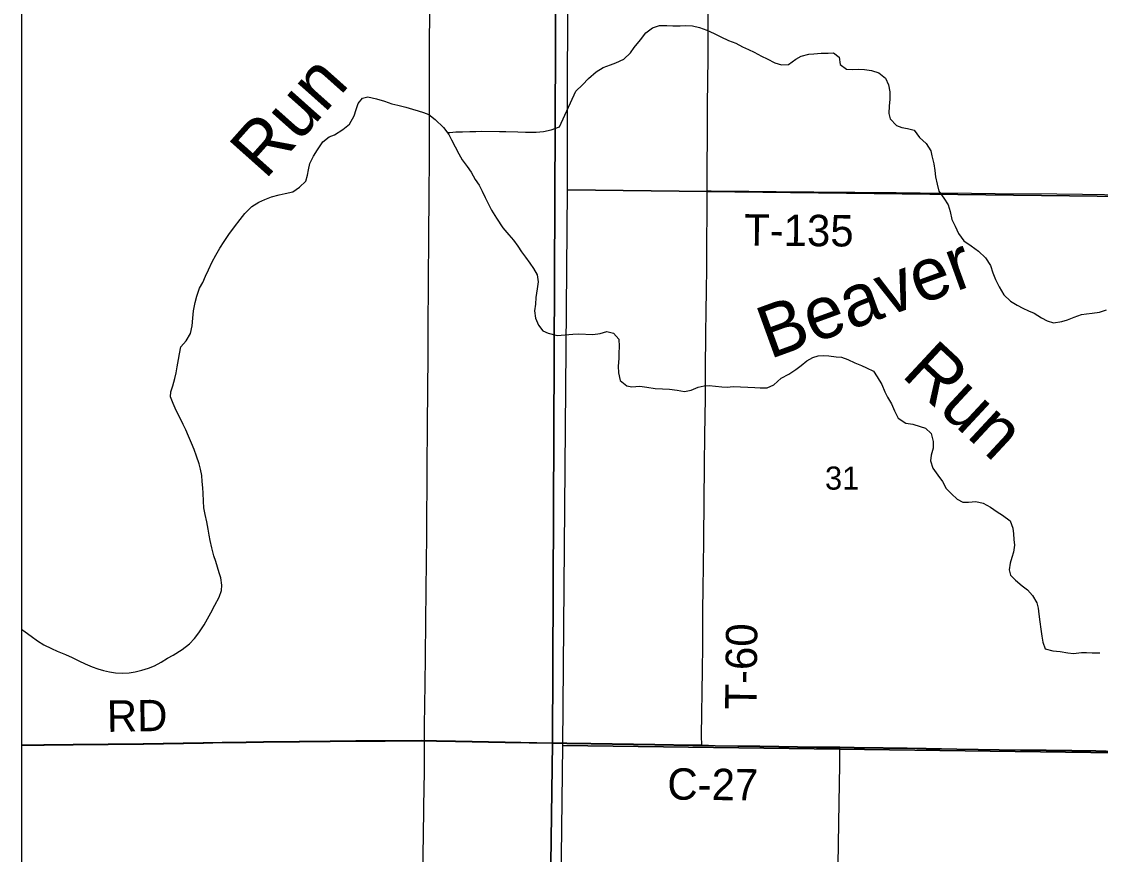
# Model space of a CAD drawing. Extents: x 0 to 34, y 0 to 22.
# Drawn here: x 2 to 3.955, y 15.508 to 17.017 of the extents above; entities that cross this region are included whole.
import ezdxf

# ---------------------------------------------------------------- set-up
doc = ezdxf.new("R2010")
doc.units = 0
for name, color, linetype in [('Default', 7, 'Continuous'), ('GM_X_City_Street', 7, 'Continuous'), ('GM_X_County_Road', 7, 'Continuous'), ('GM_X_County_Road_Text', 7, 'Continuous'), ('GM_X_Interchange_Ramps', 7, 'Continuous'), ('GM_X_Major_River_Text', 7, 'Continuous'), ('GM_X_Minor_River', 7, 'Continuous'), ('GM_X_Minor_River_Text', 7, 'Continuous'), ('GM_X_Section', 7, 'Continuous'), ('GM_X_Unincorporated_Location', 7, 'Continuous'), ('SH_Cut_Line', 7, 'Continuous'), ('SH_Text', 7, 'Continuous')]:
    doc.layers.add(name, color=color, linetype=linetype)

msp = doc.modelspace()

# ---------------------------------------------------------------- linework, layer by layer
at = {"layer": 'Default'}
for points in [[(2, 20.8), (2, 15.7064), (2.0405, 15.7068), (2.0933, 15.7073), (2.2206, 15.7088), (2.3293, 15.7107), (2.3635, 15.7113), (2.407, 15.7118), (2.4381, 15.7123), (2.5033, 15.7129), (2.5592, 15.7135), (2.6058, 15.714), (2.6587, 15.7141), (2.7239, 15.7144), (2.73, 15.7143), (2.7519, 15.714), (2.786, 15.7133), (2.8761, 15.7117), (2.9623, 15.7101), (2.9708, 17.6769)], [(2.9708, 17.6769), (2.9623, 15.7101), (2.988, 15.7097), (3.0317, 15.7091), (3.1473, 15.7074), (3.216, 15.7061), (3.2324, 15.706), (3.257, 15.7053), (3.3377, 15.7042), (3.4402, 15.7026), (3.4828, 15.7023), (3.5086, 15.702), (3.5614, 15.7014), (3.6049, 15.701), (3.639, 15.7003), (3.6949, 15.6992), (3.8099, 15.6974), (3.8565, 15.6969), (3.9031, 15.6964), (3.9466, 15.6957), (3.9843, 15.695)], [(3.9843, 15.695), (3.9466, 15.6957), (3.9031, 15.6964), (3.8565, 15.6969), (3.8099, 15.6974), (3.6949, 15.6992), (3.639, 15.7003), (3.6049, 15.701), (3.5614, 15.7014), (3.5086, 15.702), (3.4828, 15.7023), (3.4402, 15.7026), (3.3377, 15.7042), (3.257, 15.7053), (3.2324, 15.706), (3.216, 15.7061), (3.1473, 15.7074), (3.0317, 15.7091), (2.988, 15.7097), (2.9623, 15.7101), (2.9479, 14.7065), (2.9377, 14), (7.9275, 14)]]:
    msp.add_lwpolyline(points, dxfattribs=at)
msp.add_lwpolyline([(2, 15.7064), (2, 14), (2.9377, 14), (2.9479, 14.7065), (2.9623, 15.7101), (2.8761, 15.7117), (2.786, 15.7133), (2.7519, 15.714), (2.73, 15.7143), (2.7239, 15.7144), (2.6587, 15.7141), (2.6058, 15.714), (2.5592, 15.7135), (2.5033, 15.7129), (2.4381, 15.7123), (2.407, 15.7118), (2.3635, 15.7113), (2.3293, 15.7107), (2.2206, 15.7088), (2.0933, 15.7073), (2.0405, 15.7068)], close=True, dxfattribs=at)
at = {"layer": 'GM_X_City_Street'}
for points in [[(2, 15.7059), (2.0407, 15.7063), (2.0935, 15.7068), (2.2208, 15.7083), (2.3296, 15.7101), (2.3637, 15.7108), (2.4072, 15.7113), (2.4383, 15.7117), (2.5035, 15.7124), (2.5594, 15.7129), (2.6061, 15.7135), (2.6589, 15.7135), (2.7241, 15.7139), (2.7302, 15.7138)], [(2.7302, 15.7138), (2.7521, 15.7135), (2.7863, 15.7128), (2.8763, 15.7112), (2.9625, 15.7096)], [(2.9625, 15.7096), (2.9882, 15.7092), (3.0319, 15.7086), (3.1475, 15.7069), (3.2162, 15.7056), (3.2326, 15.7055)], [(3.2326, 15.7055), (3.2572, 15.7048), (3.338, 15.7037), (3.4405, 15.7021), (3.483, 15.7017)], [(3.483, 15.7017), (3.5088, 15.7015), (3.5616, 15.7008), (3.6051, 15.7005), (3.6393, 15.6998), (3.6952, 15.6987), (3.8101, 15.6969), (3.8567, 15.6963), (3.9033, 15.6959), (3.9468, 15.6952), (3.9845, 15.6945)]]:
    msp.add_lwpolyline(points, dxfattribs=at)
at = {"layer": 'GM_X_County_Road'}
msp.add_line((2.7302, 15.7049), (2.7302, 15.7138), dxfattribs=at)
for points in [[(2.7302, 15.7138), (2.7303, 15.7418), (2.7312, 15.8164), (2.7319, 15.8661), (2.7325, 15.9313), (2.7336, 16.0401), (2.7341, 16.0836), (2.7342, 16.0991), (2.7346, 16.1271), (2.735, 16.1706), (2.7351, 16.2141), (2.7358, 16.2793), (2.736, 16.357), (2.7365, 16.4036), (2.7367, 16.4347), (2.7368, 16.4626), (2.7376, 16.5434), (2.7382, 16.6304), (2.7386, 16.6988), (2.7391, 16.7733), (2.7392, 16.8137), (2.7393, 16.8697), (2.7393, 16.938), (2.7394, 16.9815), (2.7404, 17.0747)], [(2.7269, 15.4653), (2.7278, 15.5088), (2.7281, 15.543), (2.7292, 15.5896), (2.7292, 15.5958), (2.7301, 15.6579), (2.7301, 15.6921), (2.7302, 15.7049)]]:
    msp.add_lwpolyline(points, dxfattribs=at)
at = {"layer": 'GM_X_Interchange_Ramps'}
for points in [[(3.2423, 16.7102), (3.2424, 16.7422), (3.2427, 16.8199), (3.2432, 16.8665), (3.2439, 16.9504), (3.2441, 17.0032), (3.2443, 17.0405), (3.2447, 17.0746), (3.2451, 17.1399), (3.2457, 17.2176), (3.2457, 17.2673), (3.2461, 17.3605), (3.2463, 17.4196), (3.2464, 17.4631), (3.2467, 17.5625), (3.247, 17.6495), (3.247, 17.6806), (3.247, 17.6933)], [(3.2326, 15.7055), (3.2322, 15.7237), (3.2339, 15.8418), (3.2343, 15.8853), (3.2345, 15.9097), (3.2346, 15.9468), (3.2352, 15.9934), (3.2356, 16.0275), (3.236, 16.0804), (3.2376, 16.214), (3.2383, 16.2668), (3.2391, 16.3352), (3.2394, 16.388), (3.24, 16.4501), (3.2405, 16.4936), (3.241, 16.5278), (3.2417, 16.5713), (3.242, 16.6148), (3.2422, 16.6738), (3.2423, 16.7102)], [(3.2423, 16.7102), (3.2495, 16.71), (3.2557, 16.7098), (3.2836, 16.7097), (3.3178, 16.7094), (3.3674, 16.7088), (3.4357, 16.7082), (3.5846, 16.7073), (3.628, 16.7068), (3.7211, 16.7058), (3.7645, 16.7052), (3.8762, 16.7045), (3.9227, 16.7039), (4.0025, 16.7029)], [(3.4667, 14.6814), (3.467, 14.7085), (3.4673, 14.7427), (3.4682, 14.7954), (3.4685, 14.8233), (3.469, 14.845), (3.47, 14.8947), (3.4719, 15.0063), (3.473, 15.0622), (3.4738, 15.1149), (3.4746, 15.1553), (3.4754, 15.1956), (3.4765, 15.2639), (3.4774, 15.329), (3.4789, 15.4252), (3.4799, 15.4903), (3.4816, 15.602), (3.4826, 15.6703), (3.4829, 15.6946), (3.483, 15.7017)]]:
    msp.add_lwpolyline(points, dxfattribs=at)
at = {"layer": 'GM_X_Section'}
for points in [[(2.9746, 16.8262), (3.0044, 16.891), (3.0165, 16.902), (3.0275, 16.9135), (3.0411, 16.926), (3.054, 16.9336), (3.0672, 16.9386), (3.0771, 16.9421), (3.0915, 16.9486), (3.1036, 16.9604), (3.1103, 16.9699), (3.1213, 16.9836), (3.1311, 16.9961), (3.1432, 17.0052), (3.1557, 17.0098), (3.1694, 17.0095), (3.18, 17.0088), (3.1933, 17.0088), (3.2035, 17.0096), (3.2157, 17.0089), (3.2286, 17.0063), (3.2419, 17.0014), (3.2548, 16.9954), (3.2673, 16.9893), (3.281, 16.9826), (3.2943, 16.9777), (3.3061, 16.9709), (3.3175, 16.9664), (3.3277, 16.9615), (3.3407, 16.9543), (3.3509, 16.949), (3.365, 16.9423), (3.3771, 16.9381), (3.3897, 16.9393), (3.4029, 16.9488), (3.4127, 16.9538), (3.4264, 16.9576), (3.4359, 16.9581), (3.4488, 16.9596), (3.4613, 16.9597), (3.4711, 16.9604), (3.4818, 16.9521), (3.4834, 16.9389), (3.4951, 16.9306), (3.5065, 16.9298), (3.5164, 16.9303), (3.5274, 16.9299), (3.5403, 16.9284), (3.5532, 16.9239), (3.5654, 16.9145), (3.5711, 16.902), (3.5734, 16.8895), (3.5735, 16.8755), (3.572, 16.8641), (3.5717, 16.85), (3.574, 16.8406), (3.5854, 16.8288), (3.5953, 16.8247), (3.6052, 16.8228), (3.6177, 16.8199), (3.6272, 16.8066), (3.639, 16.7957), (3.6474, 16.7828), (3.6497, 16.7733), (3.6532, 16.7593), (3.6547, 16.7468), (3.6563, 16.7354), (3.659, 16.7225), (3.6621, 16.7093), (3.6709, 16.6968), (3.6789, 16.6847), (3.6827, 16.6725), (3.6858, 16.6581), (3.6919, 16.6464), (3.698, 16.6331), (3.7072, 16.6195), (3.7205, 16.6108), (3.7342, 16.601), (3.7467, 16.5886), (3.7555, 16.5749), (3.7601, 16.5617), (3.7651, 16.5496), (3.7712, 16.5363), (3.78, 16.5219), (3.7922, 16.5106), (3.8043, 16.503), (3.8142, 16.4974), (3.8249, 16.4929), (3.8351, 16.4887), (3.8484, 16.4804), (3.8583, 16.4748), (3.8701, 16.471), (3.8849, 16.4733), (3.8951, 16.4768), (3.9072, 16.4814), (3.9205, 16.486), (3.9299, 16.4875), (3.9398, 16.4887), (3.9531, 16.4903), (3.966, 16.4949)], [(2.3132, 15.8996), (2.3209, 15.9098), (2.3306, 15.9241), (2.343, 15.9459), (2.3504, 15.9595), (2.3582, 15.9745), (2.3625, 15.9862), (2.363, 15.9961), (2.3609, 16.009), (2.358, 16.0185), (2.3551, 16.0288), (2.3519, 16.0387), (2.3482, 16.0494), (2.3446, 16.0639), (2.3417, 16.0772), (2.34, 16.0867), (2.3382, 16.0973), (2.3354, 16.111), (2.3325, 16.124), (2.3304, 16.1362), (2.3294, 16.1479), (2.3289, 16.1627), (2.3282, 16.1722), (2.3272, 16.1836), (2.3266, 16.1946), (2.3245, 16.206), (2.3216, 16.2159), (2.3172, 16.2297), (2.3129, 16.2419), (2.3077, 16.2529), (2.3026, 16.2659), (2.2974, 16.2774), (2.2926, 16.2869), (2.286, 16.301), (2.2804, 16.3121), (2.2749, 16.3251), (2.2701, 16.3369), (2.2702, 16.3464), (2.2742, 16.3573), (2.2778, 16.3706), (2.2802, 16.3808), (2.2819, 16.3914), (2.2843, 16.405), (2.286, 16.4152), (2.2888, 16.4277), (2.2984, 16.4386), (2.3062, 16.4521), (2.309, 16.4654), (2.3104, 16.4798), (2.3117, 16.4927), (2.3145, 16.5078), (2.3174, 16.5195), (2.3225, 16.5339), (2.3283, 16.5444), (2.3334, 16.5557), (2.3389, 16.5674), (2.3455, 16.5814), (2.3521, 16.5934), (2.3595, 16.6066), (2.3669, 16.6183), (2.3754, 16.631), (2.3858, 16.6449), (2.3963, 16.6581), (2.4047, 16.669), (2.4174, 16.6821), (2.4297, 16.6895), (2.4408, 16.6947), (2.4526, 16.6994), (2.4667, 16.703), (2.4777, 16.7052), (2.4918, 16.7084), (2.5037, 16.717), (2.5148, 16.7278), (2.518, 16.7384), (2.52, 16.7482), (2.5225, 16.76), (2.5291, 16.7731), (2.5365, 16.7844), (2.5458, 16.7991), (2.5576, 16.8077), (2.5672, 16.8117), (2.5821, 16.821), (2.5944, 16.8311), (2.6029, 16.8458), (2.6065, 16.8578), (2.6101, 16.8684), (2.6178, 16.8782), (2.6273, 16.8803), (2.6432, 16.8771), (2.6575, 16.8723), (2.6711, 16.8676), (2.6817, 16.8652), (2.6961, 16.862), (2.7086, 16.858), (2.7184, 16.8552), (2.7282, 16.852), (2.738, 16.8485), (2.7497, 16.8396), (2.7643, 16.825), (2.7744, 16.812), (2.7792, 16.8024)], [(2.7716, 16.8156), (2.7759, 16.8161), (2.7866, 16.8171), (2.7987, 16.8169), (2.812, 16.8175), (2.8234, 16.8177), (2.834, 16.8184), (2.8659, 16.8179), (2.8776, 16.8174), (2.8993, 16.8171), (2.9129, 16.8165), (2.9232, 16.8164), (2.9326, 16.8166), (2.9459, 16.8176), (2.9596, 16.8205), (2.9746, 16.8262)], [(2.7792, 16.8024), (2.7925, 16.7772), (2.7984, 16.7665), (2.8073, 16.7542), (2.8148, 16.7443), (2.8222, 16.7305), (2.8289, 16.7205), (2.8344, 16.7095), (2.84, 16.698), (2.8455, 16.6873), (2.8518, 16.6751), (2.8603, 16.6609), (2.8722, 16.6429), (2.8831, 16.6303), (2.8913, 16.6207), (2.8991, 16.61), (2.9058, 16.6), (2.9133, 16.59), (2.9211, 16.5789), (2.9278, 16.5694), (2.9345, 16.5583), (2.9358, 16.5453), (2.9345, 16.5328), (2.932, 16.5173), (2.9311, 16.5052), (2.9294, 16.4931), (2.9315, 16.4794), (2.9367, 16.4668), (2.9445, 16.4568), (2.9543, 16.4525), (2.9705, 16.4479)], [(2.9705, 16.4479), (2.9992, 16.4503), (3.0094, 16.4514), (3.0352, 16.45), (3.0485, 16.4516), (3.0606, 16.4554), (3.0728, 16.4524), (3.0823, 16.4414), (3.0831, 16.4285), (3.0824, 16.416), (3.082, 16.4065), (3.081, 16.3925), (3.0818, 16.3804), (3.0845, 16.3664), (3.0966, 16.3569), (3.1061, 16.355), (3.1205, 16.3566), (3.1331, 16.3548), (3.1482, 16.3522), (3.1615, 16.3514), (3.174, 16.3511), (3.1881, 16.3489), (3.2014, 16.347), (3.2135, 16.3493), (3.226, 16.3547), (3.2366, 16.357), (3.2461, 16.3574), (3.2689, 16.3552), (3.2787, 16.3549), (3.2893, 16.3557), (3.3026, 16.3553), (3.3159, 16.3546), (3.3288, 16.3539), (3.3383, 16.3535), (3.3508, 16.3532), (3.3633, 16.3589), (3.3765, 16.3707), (3.3905, 16.3784), (3.403, 16.3864), (3.4129, 16.394), (3.4231, 16.402), (3.4341, 16.4081), (3.4435, 16.4112), (3.4534, 16.412), (3.4629, 16.4112), (3.4762, 16.4094), (3.4856, 16.4087), (3.4974, 16.4049), (3.51, 16.3989), (3.5217, 16.3936), (3.5312, 16.3899), (3.5438, 16.3838), (3.5506, 16.3736), (3.5587, 16.3592), (3.564, 16.3463), (3.5694, 16.3365), (3.5762, 16.3244), (3.5816, 16.3115), (3.5885, 16.2983), (3.6022, 16.2896), (3.6151, 16.2873), (3.628, 16.2836), (3.6382, 16.2802), (3.6485, 16.2708), (3.652, 16.256), (3.6516, 16.2439), (3.6483, 16.2317), (3.6468, 16.2211), (3.651, 16.2078), (3.6602, 16.195), (3.6685, 16.1836), (3.6754, 16.1711), (3.6849, 16.1613), (3.6956, 16.1518), (3.7059, 16.1462), (3.7157, 16.1462), (3.7294, 16.1474), (3.7427, 16.1444), (3.7556, 16.1372), (3.7677, 16.1286), (3.7776, 16.1229), (3.7913, 16.1123), (3.7963, 16.0991), (3.7975, 16.0892), (3.7983, 16.0786), (3.7991, 16.0687), (3.7972, 16.0558), (3.7942, 16.046), (3.7912, 16.0357), (3.7897, 16.024), (3.7917, 16.0141), (3.8012, 16.005), (3.813, 15.9945), (3.8225, 15.9873), (3.8316, 15.9771), (3.84, 15.9642), (3.8423, 15.9544), (3.8431, 15.9434), (3.8451, 15.9293), (3.8467, 15.9161), (3.849, 15.9036)], [(2, 15.9164), (2.0064, 15.9114), (2.0176, 15.9036), (2.0289, 15.8951), (2.0402, 15.8878), (2.0545, 15.8811), (2.0647, 15.8764), (2.0794, 15.8702), (2.0919, 15.8647), (2.1039, 15.8592), (2.1153, 15.8537), (2.1281, 15.8479), (2.1379, 15.8447), (2.1485, 15.8415), (2.1594, 15.8391), (2.1704, 15.8374), (2.1826, 15.8365), (2.1947, 15.8375), (2.2061, 15.8392), (2.2179, 15.8421), (2.2301, 15.8457), (2.2408, 15.8501), (2.253, 15.8564), (2.2645, 15.8639), (2.2744, 15.8694), (2.2909, 15.8794), (2.3043, 15.8899), (2.3132, 15.8996)], [(3.849, 15.9036), (3.8505, 15.8926), (3.8548, 15.8804), (3.8684, 15.8771), (3.8821, 15.876), (3.8957, 15.8737), (3.906, 15.8723), (3.9204, 15.8742), (3.9299, 15.8742), (3.9401, 15.8735), (3.9538, 15.8736)]]:
    msp.add_lwpolyline(points, dxfattribs=at)
at = {"layer": 'GM_X_Unincorporated_Location'}
for points in [[(4.0116, 17.7079), (3.9996, 16.6997), (2.9891, 16.7122), (2.9907, 17.7166)], [(3.9996, 16.6997), (3.983, 15.6924), (2.9805, 15.7055), (2.9891, 16.7122)], [(3.983, 15.6924), (3.9687, 14.6839), (3.2537, 14.69), (2.9712, 14.7039), (2.9687, 14.7038), (2.9805, 15.7055)]]:
    msp.add_lwpolyline(points, close=True, dxfattribs=at)
at = {"layer": 'SH_Cut_Line'}
msp.add_line((2, 21), (2, 14), dxfattribs=at)
at = {"layer": 'SH_Text'}
for points in [[(2.9842, 20.8), (2, 20.8), (2, 14), (2.9377, 14), (2.9479, 14.7065), (2.9623, 15.7101), (2.9708, 17.6769), (2.9753, 18.7199), (2.9796, 19.7242), (2.9904, 20.3395), (2.984, 20.7397)], [(2.9377, 14), (8.8, 14), (8.8, 20.8), (2.9842, 20.8), (2.984, 20.7397), (2.9904, 20.3395), (2.9796, 19.7242), (2.9753, 18.7199), (2.9708, 17.6769), (2.9623, 15.7101), (2.9479, 14.7065)]]:
    msp.add_lwpolyline(points, close=True, dxfattribs=at)

# ---------------------------------------------------------------- texts
at = {"layer": 'GM_X_County_Road_Text'}
for s, rotation, p in [('T-135', 359.4385, (3.309, 16.6112)), ('T-60', 89.2927, (3.3315, 15.7703))]:
    msp.add_text(s, height=0.05682, rotation=rotation, dxfattribs=at).set_placement(p)
at = {"layer": 'GM_X_Major_River_Text'}
msp.add_text('31', height=0.04186, rotation=0, dxfattribs=at).set_placement((3.4558, 16.169))
at = {"layer": 'GM_X_Minor_River'}
for s, height, rotation, p in [('Run', 0.09471, 48.2995, (2.4413, 16.7289)), ('Beaver', 0.09471, 19.9764, (3.3555, 16.4049)), ('Run', 0.09472, 317.0785, (3.5923, 16.3756))]:
    msp.add_text(s, height=height, rotation=rotation, dxfattribs=at).set_placement(p)
at = {"layer": 'GM_X_Minor_River_Text'}
for s, rotation, p in [('RD', 0.9783, (2.155, 15.7302)), ('C-27', 359.3154, (3.1699, 15.6078))]:
    msp.add_text(s, height=0.05682, rotation=rotation, dxfattribs=at).set_placement(p)

doc.saveas('drawing.dxf')
